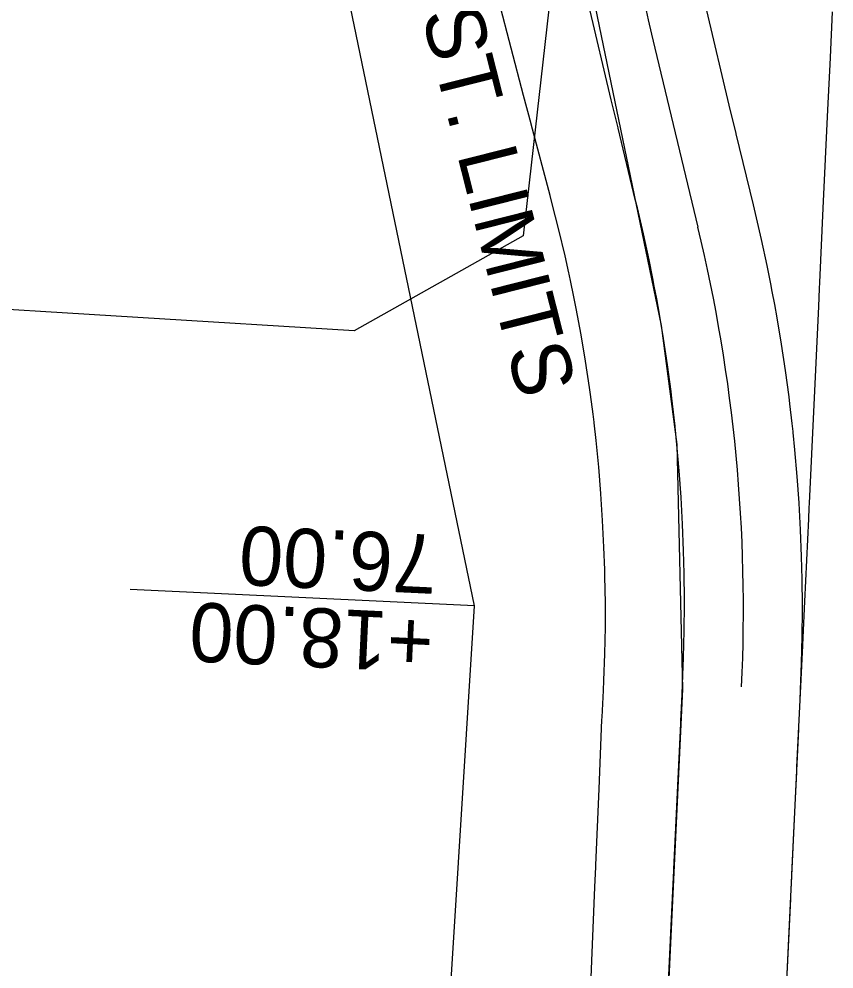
# Model space of a CAD drawing. Extents: x -70 to 701944, y -4 to 666871.
# Drawn here: x 668152.2 to 668234.9, y 654629.3 to 654725.8 of the extents above; entities that cross this region are included whole.
import ezdxf

# ---------------------------------------------------------------- set-up
doc = ezdxf.new("R2010")
doc.units = 0
for name, color, linetype in [('R_No Plot', 7, 'Continuous'), ('R_Proposed Const Limits', 7, 'Continuous'), ('R_Proposed Road', 7, 'Continuous'), ('R_ROW', 7, 'Continuous'), ('R_Temp Easement Annot', 7, 'Continuous'), ('T_Drafting', 7, 'Continuous'), ('T_Indications', 7, 'Continuous')]:
    doc.layers.add(name, color=color, linetype=linetype)

msp = doc.modelspace()

# ---------------------------------------------------------------- linework, layer by layer
at = {"layer": 'R_No Plot'}
msp.add_line((668216.737, 654722.858), (668221.121, 654704.664), dxfattribs=at)
msp.add_lwpolyline([(668278.195, 654744.537), (668206.781, 654747.907), (668207.174, 654744.1), (668217.396, 654694.687), (668218.983, 654682.598), (668219.538, 654657.721), (668214.327, 654547.329), (668268.766, 654544.759)], close=True, dxfattribs=at)
for centre, start, end in [((668378.118, 654761.744), 177.29778, 193.54759), ((668059.74, 654665.778), 357.29778, 13.54759)]:
    msp.add_arc(centre, 166, start, end, dxfattribs=at)
at = {"layer": 'R_Proposed Const Limits'}
msp.add_lwpolyline([(668210.247, 654627.61), (668210.645, 654637.603), (668210.749, 654639.684), (668210.756, 654639.831), (668211.075, 654647.594), (668211.366, 654654.611), (668211.38, 654654.882), (668211.513, 654657.584), (668211.564, 654658.612), (668211.674, 654661.32), (668211.736, 654664.029), (668211.725, 654666.741), (668211.713, 654667.586), (668211.67, 654669.452), (668211.664, 654669.655), (668211.658, 654669.847), (668211.569, 654672.163), (668211.43, 654674.873), (668211.271, 654677.579), (668211.269, 654677.618), (668211.067, 654680.283), (668210.796, 654682.984), (668210.592, 654684.772), (668210.58, 654684.864), (668210.48, 654685.682), (668210.217, 654687.679), (668210.119, 654688.375), (668209.712, 654691.063), (668209.256, 654693.745), (668208.755, 654696.421), (668208.485, 654697.771), (668208.21, 654699.089), (668208.04, 654699.882), (668208.007, 654700.033), (668207.622, 654701.749), (668206.995, 654704.401), (668206.326, 654707.043), (668206.102, 654707.895), (668204.186, 654715.144), (668204.181, 654715.161), (668203.42, 654718.033), (668200.892, 654727.667)], dxfattribs=at)
at = {"layer": 'R_Proposed Road'}
for points in [[(668218.099, 654627.24), (668218.571, 654637.229), (668218.669, 654639.311), (668218.676, 654639.457), (668219.042, 654647.218), (668219.373, 654654.233), (668219.386, 654654.504), (668219.513, 654657.206), (668219.562, 654658.235), (668219.668, 654660.943), (668219.732, 654663.652), (668219.753, 654666.362), (668219.751, 654667.206), (668219.732, 654669.072), (668219.728, 654669.275), (668219.725, 654669.467), (668219.667, 654671.781), (668219.56, 654674.489), (668219.411, 654677.195), (668219.408, 654677.234), (668219.218, 654679.898), (668218.983, 654682.598), (668218.804, 654684.384), (668218.795, 654684.476), (668218.706, 654685.294), (668218.473, 654687.289), (668218.386, 654687.985), (668218.024, 654690.671), (668217.62, 654693.35), (668217.173, 654696.023), (668216.931, 654697.373), (668216.684, 654698.689), (668216.531, 654699.481), (668216.501, 654699.632), (668216.154, 654701.347), (668215.581, 654703.996), (668214.967, 654706.635), (668214.762, 654707.486), (668213.018, 654714.727), (668213.013, 654714.744), (668212.322, 654717.613), (668210.023, 654727.236)], [(668230.086, 654626.674), (668230.557, 654636.663), (668230.655, 654638.745), (668230.662, 654638.891), (668231.029, 654646.652), (668231.36, 654653.667), (668231.373, 654653.938), (668231.5, 654656.641), (668231.549, 654657.669), (668231.655, 654660.377), (668231.719, 654663.086), (668231.74, 654665.796), (668231.738, 654666.641), (668231.718, 654668.506), (668231.715, 654668.709), (668231.712, 654668.901), (668231.654, 654671.215), (668231.547, 654673.923), (668231.397, 654676.629), (668231.395, 654676.668), (668231.205, 654679.332), (668230.97, 654682.032), (668230.791, 654683.818), (668230.781, 654683.91), (668230.693, 654684.728), (668230.46, 654686.723), (668230.373, 654687.419), (668230.011, 654690.105), (668229.606, 654692.785), (668229.16, 654695.458), (668228.918, 654696.807), (668228.671, 654698.123), (668228.517, 654698.916), (668228.488, 654699.066), (668228.141, 654700.781), (668227.568, 654703.43), (668226.954, 654706.069), (668226.749, 654706.921), (668225.004, 654714.161), (668225, 654714.179), (668224.309, 654717.047), (668222.01, 654726.67)]]:
    msp.add_lwpolyline(points, dxfattribs=at)
at = {"layer": 'R_ROW'}
msp.add_lwpolyline([(668327.662, 653586.017), (668340.866, 653592.636), (668322.469, 653689.423), (668277.131, 653821.63), (668258.714, 653853.344), (668224.548, 653854.189), (668177.848, 653978.143), (668204.742, 653982.278), (668180.351, 654096.997), (668169.324, 654193.983), (668198.414, 654666.211), (668182.924, 654741.025), (668186.49, 654858.988), (668209.004, 654933.009), (668212.484, 655027.95)], dxfattribs=at)
at = {"layer": 'R_Temp Easement Annot'}
msp.add_lwpolyline([(668198.414, 654666.211), (668163.453, 654667.861)], dxfattribs=at)
at = {"layer": 'T_Drafting'}
msp.add_lwpolyline([(668523.302, 654913.986), (668505.076, 654903.259), (668442.36, 654901.65), (668353.913, 654883.95), (668302.454, 654860.35), (668281.548, 654841.042), (668231.161, 654787.407), (668206.57, 654732.229), (668203.354, 654703.803), (668186.2, 654694.148), (668142.245, 654696.83), (668095.61, 654705.412), (668080.601, 654700.048), (668074.704, 654674.303), (668078.992, 654639.977), (668057.704, 654627.181)], dxfattribs=at)
at = {"layer": 'T_Indications'}
msp.add_lwpolyline([(668230.085, 654626.674), (668230.544, 654636.414), (668230.554, 654636.623), (668230.556, 654636.663), (668231.028, 654646.652), (668231.152, 654649.283), (668231.176, 654649.797), (668231.499, 654656.641), (668231.759, 654662.152), (668231.798, 654662.971), (668231.971, 654666.63), (668232.367, 654675.022), (668232.42, 654676.145), (668232.442, 654676.618), (668232.913, 654686.607), (668233.385, 654696.596), (668233.472, 654698.44), (668233.5, 654699.03), (668233.856, 654706.585), (668234.328, 654716.574), (668234.577, 654721.859), (668234.58, 654721.914), (668234.799, 654726.563)], dxfattribs=at)

# ---------------------------------------------------------------- texts
at = {"layer": 'R_Proposed Const Limits'}
msp.add_text('CONST. LIMITS', height=6, rotation=284.22159, dxfattribs=at).set_placement((668188.653, 654743.615))
at = {"layer": 'R_Temp Easement Annot'}
for s, p in [('76.00', (668194.749, 654673.392)), ('+18.00', (668194.372, 654665.401))]:
    msp.add_text(s, height=6, rotation=177.29778, dxfattribs=at).set_placement(p)

doc.saveas('drawing.dxf')
